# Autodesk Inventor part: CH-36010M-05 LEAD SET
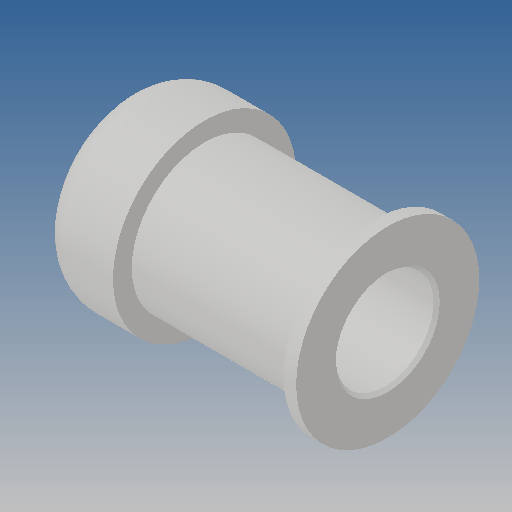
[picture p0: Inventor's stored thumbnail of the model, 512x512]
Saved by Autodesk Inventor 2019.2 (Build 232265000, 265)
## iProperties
Created: 2012-09
Part Number: CH-36010M-05 LEAD SET
Material: Ogólny
Document SubType Name: Modeling
Designer: CADENGINEERING4
Density: 1 g/cm^3
Appearance: Domyślna
Author: CADENGINEERING4
Revision Number: ÈÎºÎ
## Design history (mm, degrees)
feature "µ¹½Ç1"
node "Bryła1"
